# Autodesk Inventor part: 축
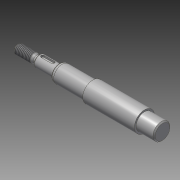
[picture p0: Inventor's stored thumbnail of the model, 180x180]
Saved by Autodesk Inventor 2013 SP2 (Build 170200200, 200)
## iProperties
Created: 2015-11
Part Number: 축
Material: 강철, 연강
Document SubType Name: Modeling
Designer: mduedu
Density: 1 g/cm^3
Author: mduedu
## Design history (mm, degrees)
sketch "스케치1"
  geometry: L1 (-89, 0)-(89, 0); L2 (-89, 0)-(-89, 4); L3 (-89, 4)-(-73.732, 4); L4 (-73.732, 4)-(-72, 3); L5 (-72, 3)-(-70, 3); L6 (-70, 3)-(-70, 5); L7 (-70, 5)-(-52, 5); L8 (-52, 5)-(-52, 6.55); L9 (-50.355, 7.5)-(-24, 7.5); L10 (-24, 7.5)-(-24, 9); L11 (0, 0)-(0, 9); L12 (89, 4)-(73.732, 4); L13 (73.732, 4)-(72, 3); L14 (72, 3)-(70, 3); L15 (70, 3)-(70, 5); L16 (70, 5)-(52, 5); L17 (24, 7.5)-(24, 9); L18 (89, 0)-(89, 4); L19 (-24, 9)-(24, 9); L20 (-52, 6.55)-(-50.355, 7.5); L21 (50.355, 7.5)-(24, 7.5); L22 (52, 6.55)-(50.355, 7.5); L23 (52, 5)-(52, 6.55); 1 further point
  constraints: 46 end point, 10 symmetric about line, 6 perpendicular, 5 parallel, 2 midpoint, 1 coincident, 1 horizontal
  dimensions: "d0" = 178 distance of L1.start L1.end (derived); "d1" = 8 diameter of L3 L1; "d2" = 30 deg angle of L4 L5; "d3" = 6 diameter of L5 L1; "d4" = 10 diameter of L7 L1; "d5" = 15 diameter of L9 L1; "d6" = 18 diameter of L19 L1; "d8" = 18 distance of L6.end L7.end; "d9" = 48 distance of L10.end L17.end; "d10" = 2 distance of L4.end L5.end; "d11" = 17 distance from line of L4.end L2; "d16" = 13.1 diameter of L8.end L1; "d17" = 30 deg angle of L20 L9; "d18" = 28 distance between parallel lines of L10 L8
revolve "회전1" sketch "스케치1" stored, may be unused: angle "d12" = 90 deg
chamfer "모따기1" distance "d13" = 1; stored, may be unused: second distance "d14" = 2, angle "d15" = 45 deg
fillet "모깎기1" dims "d19" = 4, "d20" = 0.5
node "작업 평면1"
sketch "스케치2" dims "d23" = 12
  geometry: L1 (-5.5, 1.5)-(3.5, 1.5); L2 (3.5, 1.5)-(3.5, -1.5); L3 (3.5, -1.5)-(-5.5, -1.5); L4 (-5.5, -1.5)-(-5.5, 1.5); L5 (-9, -4)-(-9, 4) reference; 3 further points
  constraints: 8 end point, 2 midpoint, 2 parallel, 2 vertical alignment, 1 horizontal, 1 perpendicular, 4 other
  dimensions: "d21" = 3 distance between parallel lines of L3 L1; "d24" = 2 dimension on L5
extrude "돌출1" cut sketch "스케치2" distance "d25" = 1.8; taper "d26" = 0 deg
feature "스레드1" dims "d27" = 10, "d28" = 0
feature "스레드2" dims "d29" = 10, "d30" = 0
chamfer "모따기2" distance "d31" = 1; stored, may be unused: second distance "d32" = 2, angle "d33" = 45 deg
node "작업 평면2"
sketch "스케치3"
  geometry: C1 r 7.5 at (0, 0) reference; 1 further point
extrude "돌출2" cut sketch "스케치3" stored distance "d36" = 10; taper "d37" = 0 deg
chamfer "모따기3" distance "d38" = 1; stored, may be unused: second distance "d39" = 2, angle "d40" = 45 deg
node "솔리드1"
mirror "대칭1"
node "절단 모서리 투영1"
other parameters: "d35" = 12
